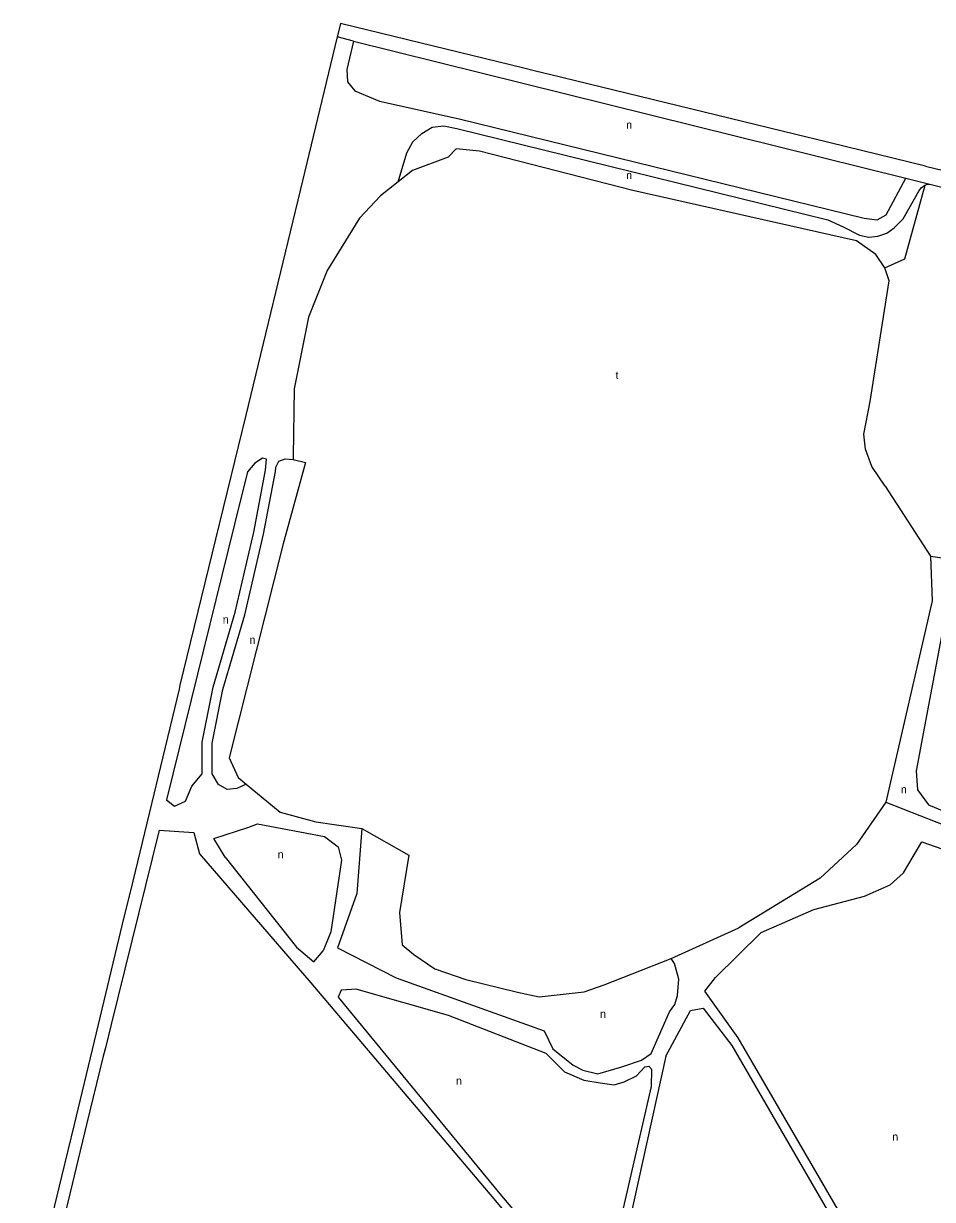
# Model space of a CAD drawing. Extents: x 153608 to 155459, y 385052 to 386919.
# Drawn here: x 153608 to 154062, y 385663 to 386250 of the extents above; entities that cross this region are included whole.
import ezdxf

# ---------------------------------------------------------------- set-up
doc = ezdxf.new("R2010")
doc.units = 0
for name, color, linetype in [('BLT_Basislijn', 7, 'Continuous'), ('BLT_Centroide', 7, 'Continuous'), ('BLT_Gemeentegrens', 7, 'Continuous')]:
    doc.layers.add(name, color=color, linetype=linetype)

msp = doc.modelspace()

# ---------------------------------------------------------------- linework, layer by layer
at = {"layer": 'BLT_Basislijn'}
for p, q in [((153772.84, 386241.32), (153764.63, 386243.42)), ((153772.84, 386241.32), (154048.84, 386172.83)), ((154048.84, 386172.83), (154058.83, 386170.35)), ((154058.83, 386170.35), (154060.93, 386169.83)), ((153761.41, 385796.25), (153757.54, 385786.8)), ((153648.72, 385738.31), (153647.69, 385734.14))]:
    msp.add_line(p, q, dxfattribs=at)
for points in [[(153772.84, 386241.32), (153769.35, 386227.18)], [(153769.35, 386227.18), (153769.77, 386220.98), (153773.47, 386216.58), (153785.81, 386211.35), (153825.56, 386202.5), (154027.98, 386152.84), (154034.56, 386152.12), (154039.07, 386154.59), (154048.84, 386172.83)], [(153795.1, 386171.02), (153799.35, 386185.54), (153802.45, 386191.1), (153806.9, 386195.27), (153812.07, 386198.37), (153817.88, 386199.09), (153824.42, 386197.63), (154009.87, 386152.13), (154017.63, 386148.56), (154025.73, 386144.36), (154030.32, 386143.47), (154034.9, 386143.82), (154039.32, 386145.41), (154043.07, 386148.02), (154047.49, 386152.48), (154055.36, 386166.3), (154056.51, 386167.99), (154058.31, 386169.33), (154058.58, 386169.43)], [(153820.06, 386183.31), (153802.29, 386176.74), (153795.1, 386171.02)], [(154024.29, 386141.5), (153912.47, 386166.67), (153835.81, 386186.33), (153824.13, 386187.6), (153820.06, 386183.31)], [(153795.1, 386171.02), (153786.26, 386164), (153775.72, 386152.94), (153759.57, 386126.72), (153750.18, 386103.35), (153743.08, 386067.67), (153742.66, 386034.02), (153742.64, 386032.29)], [(154038.47, 386128.14), (154048.47, 386132.65), (154058.58, 386169.43)], [(154058.58, 386169.43), (154059.6, 386169.81), (154060.93, 386169.83)], [(154060.93, 386169.83), (154073.68, 386166.67), (154428.43, 386078.64)], [(154038.47, 386128.14), (154033.83, 386134.76), (154024.29, 386141.5)], [(154038.55, 386019.01), (154031.82, 386028.87), (154028.69, 386037.46), (154027.84, 386044.97), (154031.11, 386061.23), (154040.53, 386121.64), (154038.47, 386128.14)], [(153697.14, 385875.28), (153697.14, 385891.1), (153702.64, 385918.62), (153713.63, 385956), (153722.88, 385996.07), (153728.84, 386027.01), (153729.26, 386032.54), (153727.34, 386032.96), (153723.37, 386030.49), (153719.73, 386026.07)], [(153719.11, 385870.15), (153714.4, 385867.93), (153709.6, 385867.45), (153705.24, 385869.92), (153702.14, 385875.28), (153702.14, 385890.61), (153707.5, 385917.42), (153718.47, 385954.73), (153727.77, 385995.03), (153733.8, 386026.34), (153733.97, 386028.49), (153735.37, 386031.54), (153738.63, 386032.72), (153742.64, 386032.29)], [(153742.64, 386032.29), (153748.82, 386030.85), (153737.64, 385990.22)], [(153719.73, 386026.07), (153713.3, 386000), (153679.3, 385862.24), (153683.21, 385859.08), (153688.84, 385861.6), (153692, 385869.1), (153697.14, 385875.28)], [(154038.55, 386019.01), (154061.3, 385983.98)], [(153737.64, 385990.22), (153710.53, 385883.16)], [(154061.3, 385983.98), (154062.03, 385961.65), (154038.94, 385861.11)], [(154061.3, 385983.98), (154073.89, 385982.25)], [(154073.89, 385982.25), (154053.98, 385876.82), (154054.7, 385867.21), (154060.23, 385859.76), (154115.02, 385837.17), (154142.08, 385701.54), (154161.36, 385694.78)], [(153710.53, 385883.16), (153715.15, 385873.42), (153719.11, 385870.15)], [(153719.11, 385870.15), (153736.16, 385856.09), (153753.96, 385851.23), (153776.98, 385847.93)], [(154038.94, 385861.11), (154024.22, 385839.9), (154006.07, 385823.07), (153965.42, 385798.34)], [(154038.94, 385861.11), (154106.86, 385834.44), (154134.59, 385677.64)], [(153708.66, 385833.64), (153702.91, 385842.99), (153720.41, 385848.58), (153724.69, 385850.19), (153758.18, 385843.96), (153765.07, 385838.79), (153766.78, 385832.1), (153761.41, 385796.25)], [(153776.98, 385847.93), (153774.45, 385815.41), (153764.68, 385788.34), (153794.17, 385773.39), (153868.09, 385746.75), (153872.37, 385737.79), (153882.65, 385729.66), (153887.36, 385727.22), (153894.83, 385725.41), (153906.98, 385728.78), (153916.74, 385732.11), (153921.49, 385735.54), (153930.74, 385756.34), (153933.46, 385760.06), (153934.81, 385764.55), (153935.48, 385772.71), (153933.16, 385780.44), (153931.53, 385782.99)], [(153776.98, 385847.93), (153800.4, 385834.58)], [(153675.58, 385847.17), (153651.61, 385750), (153648.72, 385738.31)], [(153675.58, 385847.17), (153693.01, 385846.01), (153695.71, 385835.2), (153751.5, 385770.79)], [(154036.15, 385621), (153965.08, 385743.39), (153948.41, 385766.59), (153953.77, 385773.54), (153976.51, 385795.97), (154002.85, 385807.54), (154028.24, 385814.09), (154041.04, 385819.77), (154047.68, 385825.72), (154056.95, 385841.28), (154097.32, 385827.18), (154127.02, 385671.7), (154150.21, 385660.41)], [(153708.66, 385833.64), (153744.28, 385788.6), (153752.99, 385781.3), (153757.54, 385786.8)], [(153800.4, 385834.58), (153795.82, 385805.89), (153797.05, 385789.88), (153802.91, 385785.05), (153813.45, 385777.79), (153828.85, 385772.51), (153854.77, 385766.22), (153865.62, 385763.76)], [(153931.53, 385782.99), (153965.42, 385798.34)], [(153898.01, 385769.85), (153931.53, 385782.99)], [(153751.5, 385770.79), (153843.75, 385661.84), (153893.6, 385601.78)], [(153774.39, 385767.72), (153766.56, 385767.07), (153765.11, 385763.64), (153846.81, 385664.42), (153893.06, 385609.65)], [(153774.39, 385767.72), (153820.04, 385754.64), (153868.83, 385735.67), (153878.18, 385726.32), (153887.88, 385722.13), (153896.08, 385720.82), (153903, 385719.8), (153908.15, 385721.39), (153914.3, 385724.3), (153918.46, 385728.9)], [(153865.62, 385763.76), (153888.06, 385766.32), (153898.01, 385769.85)], [(153928.9, 385734.11), (153941.31, 385757.04), (153947.55, 385758.21), (153961.97, 385739.49), (154015.29, 385647.58)], [(153647.69, 385734.14), (153639.27, 385700), (153615.64, 385601.61), (153613.38, 385592.94)], [(153928.9, 385734.11), (153908.09, 385639.7), (153895.87, 385606.32)], [(153918.46, 385728.9), (153920.45, 385729.22), (153921.73, 385727.65), (153921.64, 385719.08), (153903.28, 385639.34), (153893.06, 385609.65)]]:
    msp.add_lwpolyline(points, dxfattribs=at)
at = {"layer": 'BLT_Gemeentegrens'}
msp.add_line((153685.54, 385917.5), (153662.4, 385821.64), dxfattribs=at)
for points in [[(153766.25, 386250.15), (153766.22, 386250), (153764.63, 386243.42)], [(153863.83, 386226.4), (153857.96, 386227.83), (153766.87, 386250), (153766.25, 386250.15)], [(153764.63, 386243.42), (153746.08, 386166.67), (153718.87, 386054.43)], [(153961.09, 386202.73), (153870.73, 386224.72), (153863.83, 386226.4)], [(154058.77, 386178.94), (154002.88, 386192.55), (154000, 386193.26), (153961.09, 386202.73)], [(154058.77, 386178.94), (154109.18, 386166.68), (154165.43, 386152.97)], [(153718.87, 386054.43), (153705.81, 386000.59), (153705.67, 386000), (153686.01, 385919.47), (153685.54, 385917.5)], [(153662.4, 385821.64), (153657.19, 385800.07), (153645.11, 385750), (153633.04, 385700), (153626.79, 385674.1)], [(153626.79, 385674.1), (153607.79, 385595.38)]]:
    msp.add_lwpolyline(points, dxfattribs=at)

# ---------------------------------------------------------------- texts
at = {"layer": 'BLT_Centroide'}
for s, p in [('n', (153909.07, 386197.58)), ('n', (153909.07, 386172.43)), ('t', (153903.79, 386072.49)), ('n', (153707.4, 385950.35)), ('n', (153720.77, 385940.16)), ('n', (154046.4, 385865.48)), ('n', (153734.88, 385832.99)), ('n', (153896.01, 385753.31)), ('n', (153823.99, 385719.9)), ('n', (154042.1, 385691.95))]:
    msp.add_text(s, height=4, dxfattribs=at).set_placement(p)

doc.saveas('drawing.dxf')
